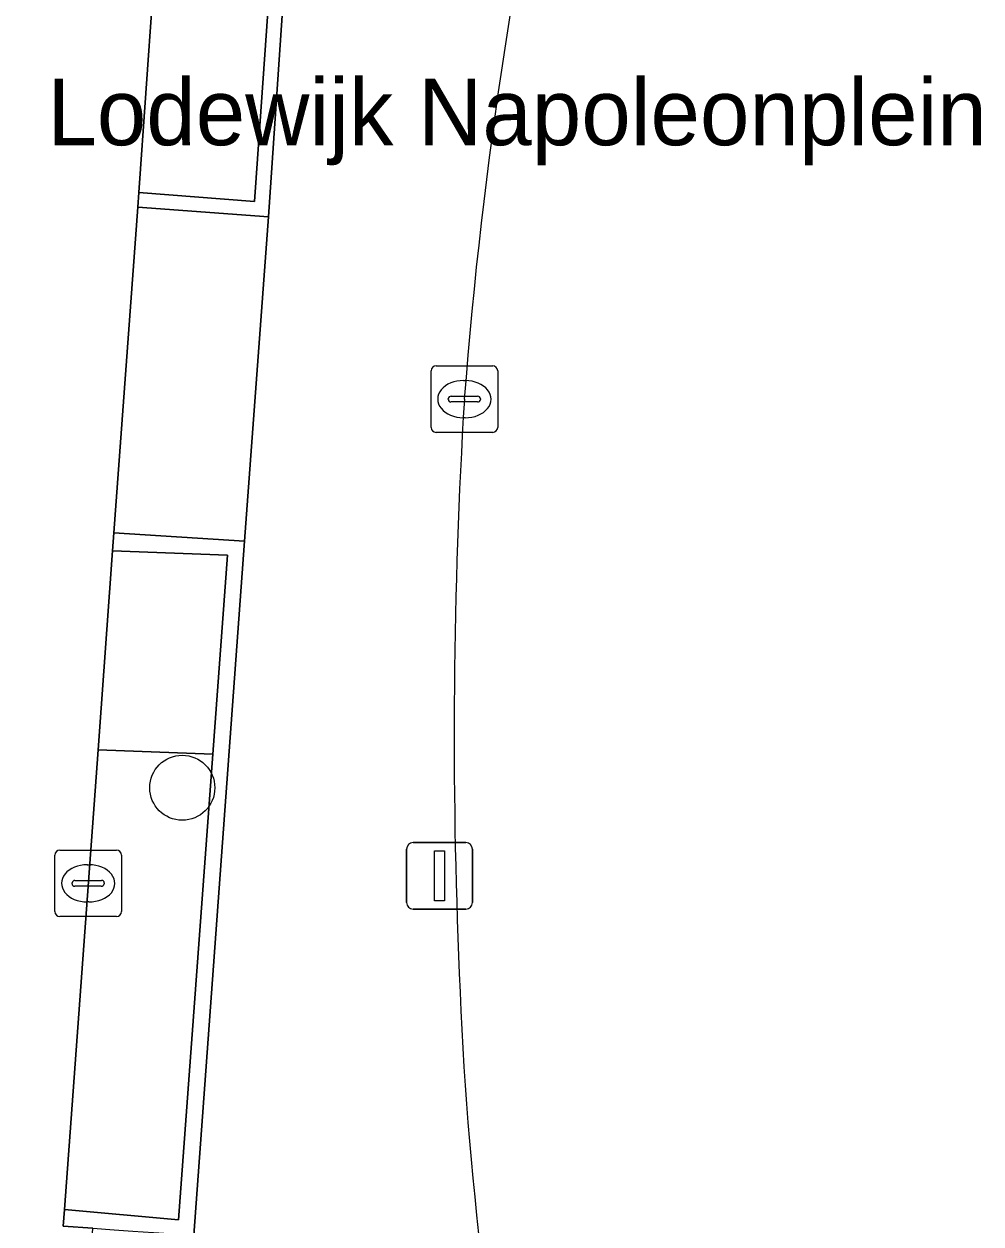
# Model space of a CAD drawing. Extents: x 159960 to 160866, y 382700 to 383354.
# Drawn here: x 160556.18 to 160570.57, y 383077.15 to 383095.2 of the extents above; entities that cross this region are included whole.
import ezdxf

# ---------------------------------------------------------------- set-up
doc = ezdxf.new("R2010")
doc.units = 0
for name, color, linetype in [('IMGEO_Boom', 7, 'Continuous'), ('IMGEO_Groenvoorziening', 7, 'Continuous'), ('IMGEO_Kolk', 7, 'Continuous'), ('IMGEO_Lichtmast', 7, 'Continuous'), ('IMGEO_Muur', 7, 'Continuous'), ('IMGEO_Openbare_ruimte_label', 7, 'Continuous'), ('IMGEO_Parkeervlak_open', 7, 'Continuous'), ('IMGEO_Voetpad_open', 7, 'Continuous')]:
    doc.layers.add(name, color=color, linetype=linetype)

msp = doc.modelspace()

# ---------------------------------------------------------------- linework, layer by layer
at = {"layer": 'IMGEO_Boom'}
msp.add_circle((160558.56, 383083.71), 0.489, dxfattribs=at)
at = {"layer": 'IMGEO_Groenvoorziening'}
for points in [[(160557.906, 383092.661), (160559.645, 383092.529), (160559.856, 383095.522), (160558.115, 383095.654)], [(160559.019, 383084.215), (160559.239, 383087.209), (160557.513, 383087.274), (160557.294, 383084.28)], [(160556.788, 383077.364), (160558.504, 383077.213), (160559.019, 383084.215), (160557.294, 383084.28)]]:
    msp.add_lwpolyline(points, close=True, dxfattribs=at)
at = {"layer": 'IMGEO_Kolk'}
for p, q in [((160562.376, 383090.055), (160563.228, 383090.055)), ((160562.301, 383089.129), (160562.301, 383089.981)), ((160562.789, 383089.835), (160562.814, 383089.835)), ((160563.302, 383089.981), (160563.302, 383089.129)), ((160562.56, 383089.549), (160562.56, 383089.561)), ((160562.998, 383089.512), (160562.6, 383089.512)), ((160562.603, 383089.598), (160563.001, 383089.598)), ((160563.044, 383089.561), (160563.044, 383089.549)), ((160562.812, 383089.275), (160562.787, 383089.275)), ((160563.228, 383089.055), (160562.376, 383089.055)), ((160556.719, 383082.772), (160557.571, 383082.772)), ((160556.644, 383081.846), (160556.644, 383082.698)), ((160557.645, 383082.698), (160557.645, 383081.846)), ((160557.132, 383082.552), (160557.157, 383082.552)), ((160556.903, 383082.266), (160556.903, 383082.278)), ((160557.341, 383082.229), (160556.943, 383082.229)), ((160556.946, 383082.315), (160557.344, 383082.315)), ((160557.387, 383082.278), (160557.387, 383082.266)), ((160557.155, 383081.992), (160557.13, 383081.992)), ((160557.571, 383081.772), (160556.719, 383081.772))]:
    msp.add_line(p, q, dxfattribs=at)
for points in [[(160562.376, 383090.055), (160563.228, 383090.055)], [(160562.301, 383089.129), (160562.301, 383089.981)], [(160563.302, 383089.981), (160563.302, 383089.129)], [(160563.228, 383089.055), (160562.376, 383089.055)], [(160556.719, 383082.772), (160557.571, 383082.772)], [(160556.644, 383081.846), (160556.644, 383082.698)], [(160557.645, 383082.698), (160557.645, 383081.846)], [(160557.571, 383081.772), (160556.719, 383081.772)]]:
    msp.add_lwpolyline(points, dxfattribs=at)
for centre, radius, start, end in [((160562.378, 383089.979), 0.0765, 91.552, 178.448), ((160562.378, 383089.979), 0.0765, 91.552, 178.448), ((160563.226, 383089.979), 0.0765, 1.552, 88.448), ((160563.226, 383089.979), 0.0765, 1.552, 88.448), ((160562.6, 383089.558), 0.0403, 85.8775, 175.7526), ((160562.597, 383089.548), 0.0366, 178.938, 274.7102), ((160563.001, 383089.555), 0.043, 264.8664, 352.4533), ((160563.005, 383089.56), 0.0386, 1.7309, 96.639), ((160562.378, 383089.131), 0.0765, 181.552, 268.448), ((160562.378, 383089.131), 0.0765, 181.552, 268.448), ((160563.226, 383089.131), 0.0765, 271.552, 358.448), ((160563.226, 383089.131), 0.0765, 271.552, 358.448), ((160556.721, 383082.696), 0.0765, 91.552, 178.448), ((160556.721, 383082.696), 0.0765, 91.552, 178.448), ((160557.569, 383082.696), 0.0765, 1.552, 88.448), ((160557.569, 383082.696), 0.0765, 1.552, 88.448), ((160556.943, 383082.275), 0.0403, 85.8775, 175.7526), ((160556.94, 383082.265), 0.0366, 178.938, 274.7102), ((160557.344, 383082.272), 0.043, 264.8664, 352.4533), ((160557.348, 383082.277), 0.0386, 1.7309, 96.639), ((160556.721, 383081.848), 0.0765, 181.552, 268.448), ((160556.721, 383081.848), 0.0765, 181.552, 268.448), ((160557.569, 383081.848), 0.0765, 271.552, 358.448), ((160557.569, 383081.848), 0.0765, 271.552, 358.448)]:
    msp.add_arc(centre, radius, start, end, dxfattribs=at)
for centre, major_axis, ratio, start_param, end_param in [((160562.788, 383089.555), (-0.387, 0.002), 0.722429, 4.712389, 7.853982), ((160562.813, 383089.555), (-0.39, 0.002), 0.717154, 1.570796, 4.712389), ((160557.131, 383082.272), (-0.387, 0.002), 0.722429, 4.712389, 7.853982), ((160557.156, 383082.272), (-0.39, 0.002), 0.717154, 1.570796, 4.712389)]:
    msp.add_ellipse(centre, major_axis=major_axis, ratio=ratio, start_param=start_param, end_param=end_param, dxfattribs=at)
at = {"layer": 'IMGEO_Lichtmast'}
for p, q in [((160561.932, 383081.984), (160561.932, 383082.784)), ((160561.932, 383082.784), (160561.932, 383081.984)), ((160562.032, 383082.884), (160562.822, 383082.884)), ((160562.822, 383082.884), (160562.032, 383082.884)), ((160562.922, 383082.784), (160562.922, 383081.984)), ((160562.922, 383081.984), (160562.922, 383082.784)), ((160562.822, 383081.884), (160562.032, 383081.884)), ((160562.032, 383081.884), (160562.822, 383081.884))]:
    msp.add_line(p, q, dxfattribs=at)
msp.add_lwpolyline([(160562.352, 383082.759), (160562.502, 383082.759), (160562.502, 383082.009), (160562.352, 383082.009), (160562.352, 383082.759)], dxfattribs=at)
for centre, start, end in [((160562.032, 383082.784), 90, 180), ((160562.032, 383082.784), 90, 180), ((160562.822, 383082.784), 0, 90), ((160562.822, 383082.784), 360, 90), ((160562.032, 383081.984), 180, 270), ((160562.032, 383081.984), 180, 270), ((160562.822, 383081.984), 270, 0), ((160562.822, 383081.984), 270, 0)]:
    msp.add_arc(centre, 0.1, start, end, dxfattribs=at)
at = {"layer": 'IMGEO_Muur'}
for points in [[(160557.891, 383092.443), (160559.854, 383092.296), (160560.561, 383102.717), (160560.306, 383102.741), (160560.014, 383102.77), (160559.683, 383102.802), (160559.389, 383102.83), (160559.055, 383102.863), (160558.622, 383102.905), (160558.604, 383102.653), (160560.35, 383102.53), (160559.856, 383095.522), (160559.645, 383092.529), (160557.906, 383092.661)], [(160559.497, 383087.418), (160557.53, 383087.544), (160557.513, 383087.274), (160559.239, 383087.209), (160559.019, 383084.215), (160558.504, 383077.213), (160556.788, 383077.364), (160556.77, 383077.113), (160557.216, 383077.083), (160557.538, 383077.061), (160557.818, 383077.042), (160558.127, 383077.021), (160558.444, 383077), (160558.734, 383076.98)]]:
    msp.add_lwpolyline(points, close=True, dxfattribs=at)
at = {"layer": 'IMGEO_Parkeervlak_open'}
msp.add_lwpolyline([(160557.891, 383092.443), (160557.53, 383087.544), (160559.497, 383087.418), (160559.854, 383092.296)], close=True, dxfattribs=at)
at = {"layer": 'IMGEO_Voetpad_open'}
for points in [[(160564.128, 383110.297), (160564.149, 383110.069), (160564.173, 383109.841), (160563.949, 383109.827), (160562.889, 383107.63), (160562.05, 383105.219), (160562.204, 383105.052), (160562.041, 383104.877), (160560.852, 383106.259), (160560.561, 383102.717), (160559.854, 383092.296), (160559.497, 383087.418), (160558.734, 383076.98), (160558.48, 383073.5), (160559.664, 383074.512), (160559.813, 383074.234), (160556.324, 383071.343), (160556.854, 383070.654), (160556.966, 383070.907), (160557.133, 383070.804)], [(160556.854, 383070.654), (160556.324, 383071.343), (160556.18, 383071.535), (160556.865, 383072.12), (160557.216, 383077.083), (160556.77, 383077.113), (160556.788, 383077.364), (160557.294, 383084.28), (160557.513, 383087.274), (160557.53, 383087.544), (160557.891, 383092.443), (160557.906, 383092.661), (160558.115, 383095.654), (160558.604, 383102.653), (160558.622, 383102.905), (160559.055, 383102.863), (160559.474, 383107.861), (160559.035, 383108.371), (160559.23, 383108.514), (160561.91, 383105.383), (160561.989, 383105.642), (160562.07, 383105.9)]]:
    msp.add_lwpolyline(points, dxfattribs=at)
for centre, radius, start, end in [((160632.464, 383084.215), 69.868, 166.90321, 175.61677), ((160632.464, 383084.215), 69.868, 166.90321, 175.61677), ((160646.044, 383084.502), 83.396, 176.52631, 182.46585), ((160646.044, 383084.502), 83.396, 176.52631, 182.46585), ((160616.045, 383082.911), 53.358, 182.1453, 191.778), ((160616.045, 383082.911), 53.358, 182.1453, 191.778)]:
    msp.add_arc(centre, radius, start, end, dxfattribs=at)

# ---------------------------------------------------------------- texts
at = {"layer": 'IMGEO_Openbare_ruimte_label'}
msp.add_text('Lodewijk Napoleonplein', height=1, dxfattribs=at).set_placement((160556.531, 383093.374))

doc.saveas('drawing.dxf')
